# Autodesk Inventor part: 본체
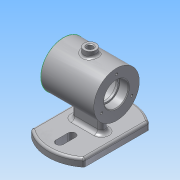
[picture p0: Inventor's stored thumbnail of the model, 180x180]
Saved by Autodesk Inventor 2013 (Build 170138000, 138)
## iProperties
Created: 2017-12
Part Number: 본체
Material: 알루미늄 6061
Document SubType Name: Modeling
Designer: Administrator
Mass: 467.691 g
Surface Area: 486.469 cm^2
Volume: 172.58 cm^3
Density: 2.71 g/cm^3
Author: Administrator
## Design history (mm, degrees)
sketch "스케치1"
  geometry: L1 (0, 0)-(0, 30); L2 (0, 0)-(70, 0); L3 (0, 30)-(70, 30); L4 (70, 0)-(70, 30); L5 (0, 16)-(12, 16); L6 (12, 16)-(12, 14); L7 (12, 14)-(15, 14); L8 (15, 14)-(15, 25); L9 (15, 25)-(55, 25); L10 (55, 25)-(55, 14); L11 (55, 14)-(58, 14); L12 (58, 14)-(58, 16); L13 (58, 16)-(70, 16)
  constraints: 26 end point, 6 parallel, 6 perpendicular, 2 point on line, 1 vertical
  dimensions: "d0" = 70 distance of L1.start L2.end; "d2" = 60 diameter of L1.end L2; "d3" = 12 distance between parallel lines of L1 L6; "d4" = 12 distance between parallel lines of L4 L12; "d5" = 3 distance of L11.end L10.end; "d6" = 3 distance of L7.end L6.end; "d7" = 50 diameter of L9 L2; "d8" = 32 diameter of L5 L2; "d9" = 32 diameter of L13 L2; "d10" = 28 diameter of L11 L2; "d11" = 28 diameter of L7 L2
revolve "회전1" sketch "스케치1" stored, may be unused: angle "d12" = 90 deg
sketch "스케치3"
  geometry: C1 r 30 at (0, 0) reference; C2 r 16 at (0, 0) reference
node "작업 평면1"
node "작업 평면2"
sketch "스케치5"
  geometry: L1 (35, 77)-(35, -77) reference; L2 (8.773, 48.344)-(61.227, 48.344); L3 (70, 42.426)-(70, -42.426); L4 (61.227, -48.344)-(8.773, -48.344); L5 (0, -42.426)-(0, 42.426); L6 (0, 48.344)-(70, -48.344); L7 (70, 48.344)-(0, -48.344); A1 r 55 centre (35, 0) between (0, -42.426) and (70, -42.426); A2 r 55 centre (35, 0) between (70, 42.426) and (0, 42.426); 1 further point
  constraints: 12 end point, 8 point on circle, 3 midpoint, 2 centre point, 2 parallel, 1 horizontal, 1 horizontal alignment, 1 perpendicular
  dimensions: "d27" = 70 distance of L6.start L7.start; "d28" = 96.68842 distance between parallel lines of L4 L2; "d29" = 55 radius of A2; "d30" = 55 radius of A1; "d31" = 84.85281 distance of L3.start L3.end; "d32" = 84.85281 distance of L5.start L5.end; "d33" = 52.45331 distance of L2.start L2.end
extrude "돌출1" join sketch "스케치5" distance "d34" = 10; taper "d35" = 0 deg
sketch "스케치6"
  geometry: L1 (20, 5)-(50, 5); L2 (50, 5)-(50, -5); L3 (50, -5)-(20, -5); L4 (20, -5)-(20, 5); L5 (20, 5)-(50, -5); L6 (50, 5)-(20, -5); L7 (35, 0)-(35, 65.234); L8 (35, 0)-(35, -72.623); L9 (-4.69, -24)-(75.323, -24); L10 (-11.445, 24)-(85.879, 24); L11 (-7.856, 40)-(85.879, 40); L12 (-5.956, -40)-(96.857, -40); L13 (30, -24)-(30, -40); L14 (40, -24)-(40, -40); L15 (30, 40)-(30, 24); L16 (40, 40)-(40, 24); A1 r 55 centre (35, 0) between (0, -42.426) and (70, -42.426) reference; A2 r 5 centre (35, 40) between (40, 40) and (30, 40); A3 r 5 centre (35, -40) between (30, -40) and (40, -40); A4 r 5 centre (35, 24) between (30, 24) and (40, 24); A5 r 5 centre (35, -24) between (40, -24) and (30, -24); 3 further points
  constraints: 32 end point, 16 point on line, 8 point on circle, 6 parallel, 4 centre point, 4 midpoint, 2 perpendicular, 2 vertical alignment, 1 collinear, 1 horizontal, 4 other
  dimensions: "d36" = 30 distance of L2.end L3.end; "d37" = 10 distance between parallel lines of L3 L1; "d38" = 24 distance from line of point (50, 0) L10; "d39" = 24 distance from line of point (50, 0) L9; "d40" = 16 distance between parallel lines of L12 L9; "d41" = 16 distance between parallel lines of L11 L10; "d42" = 10 diameter of A2; "d43" = 10 diameter of A3; "d45" = 10 diameter of A4; "d46" = 10 diameter of A5
extrude "돌출2" join sketch "스케치6" stored distance "d47" = 10; taper "d48" = 0 deg
extrude "돌출3" cut sketch "스케치6" distance "d49" = 10; taper "d50" = 0 deg
node "작업 평면3"
sketch "스케치7"
  geometry: C1 r 8 at (35, 0); 1 further point
  constraints: 1 centre point, 1 horizontal alignment
  dimensions: "d52" = 35 distance of C1.centre point (0, 0); "d53" = 16 diameter of C1
extrude "돌출4" join sketch "스케치7" stored distance "d54" = 10; taper "d55" = 0 deg
sketch "스케치8"
  geometry: C1 r 8 at (0, 0) reference; C2 r 4 at (0, 0); 1 further point
  constraints: 1 centre point, 1 coincident
  dimensions: "d56" = 8 diameter of C2
extrude "돌출5" cut sketch "스케치8" stored distance "d57" = 10; taper "d58" = 0 deg
sketch "스케치9"
  geometry: L1 (0, 0)-(26.839, -46.487); L2 (0, 0)-(20.598, 35.676); L3 (0, 0)-(-64.215, 0); C1 r 16 at (0, 0) reference; C2 r 30 at (0, 0) reference; A1 r 23 centre (0, 0) between (-23, 0) and (11.5, -19.919); 1 further point
  constraints: 6 end point, 5 point on line, 3 point on circle, 1 centre point, 1 coincident, 1 horizontal
  dimensions: "d61" = 120 deg angle of L3 L1; "d62" = 120 deg angle of L2 L3; "d63" = 46 diameter of A1
hole "구멍2" sketch "스케치9" at (-23, 0), (11.5, -19.919), (11.5, 19.919) diameter "d65" = 3.242; stored, may be unused: countersink angle "d69" = 90 deg, drill point angle "d71" = 118 deg; dims "d66" = 8, "d67" = 4, "d68" = 2, "d70" = 10
fillet "모깎기1" dims "d72" = 5
fillet "모깎기2" dims "d73" = 3
fillet "모깎기3" dims "d74" = 3
fillet "모깎기4" dims "d75" = 3
chamfer "모따기1" distance "d76" = 1; stored, may be unused: second distance "d77" = 2, angle "d78" = 45 deg
fillet "모깎기5" dims "d79" = 3
fillet "모깎기6" dims "d80" = 0.3
fillet "모깎기7" dims "d81" = 0.3
node "작업 평면4"
sketch "스케치11"
  geometry: L1 (-70, 30)-(-70, -30) reference; L2 (0, 30)-(-70, 30) reference; 2 further points
  constraints: 1 other
  dimensions: "d83" = 35 distance from line of point (-35, 0) L1; "d84" = 30 distance from line of point (-35, 0) L2
feature "엠보싱1" sketch "스케치11" dims "d85" = 0.5, "d86" = 0
node "솔리드1"
mirror "대칭2"
other parameters: "d25" = -62, "d51" = 37
